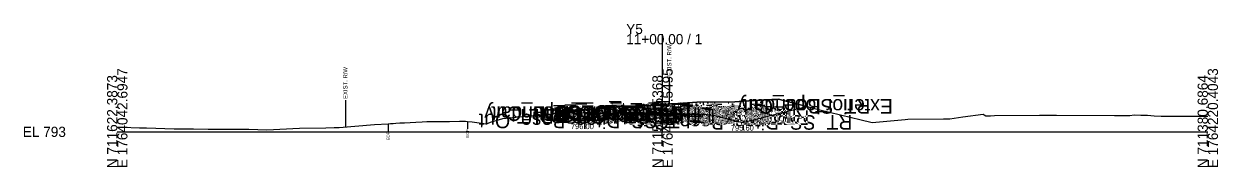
# Model space of a CAD drawing. Extents: x -26 to 303, y -10 to 4039.
# Drawn here: x -25.7 to 302.8, y 990.3 to 1029.7 of the extents above; entities that cross this region are included whole.
import ezdxf

# ---------------------------------------------------------------- set-up
doc = ezdxf.new("R2010")
doc.units = 0
for name, color, linetype in [('Default', 7, 'Continuous'), ('Exist Cross Section Cell', 7, 'Continuous'), ('Exist XS Center Line Elevation Label', 7, 'Continuous'), ('Exist XS Ground Line', 7, 'Continuous'), ('Old_Level_10', 7, 'Continuous'), ('Prop CMT Pvmt Course 1', 7, 'Continuous'), ('Prop CMT Pvmt Course 3', 7, 'Continuous'), ('Prop CMT Pvmt Surface', 7, 'Continuous'), ('Prop CMT Pvmt Surface Shoulder', 7, 'Continuous'), ('Prop CMT Shld Paved Course 1', 7, 'Continuous'), ('Prop CMT Shld Paved Course 3', 7, 'Continuous'), ('Prop CMT Slope Grass', 7, 'Continuous'), ('Prop CMT Subgrade Earthwork', 7, 'Continuous'), ('Prop XS Ditch Standard Text', 7, 'Continuous'), ('Prop XS Earthwork Shape', 7, 'Continuous'), ('Prop XS SE Text', 7, 'Continuous'), ('Prop XS Side Slope Text', 7, 'Continuous'), ('Scratch_Level_4', 7, 'Continuous')]:
    doc.layers.add(name, color=color, linetype=linetype)

msp = doc.modelspace()

# ---------------------------------------------------------------- linework, layer by layer
at = {"layer": 'Exist Cross Section Cell'}
for p, q in [((150, 1000), (150, 1026.88)), ((0, 1000), (150, 1000)), ((150, 1000), (300, 1000))]:
    msp.add_line(p, q, dxfattribs=at)
at = {"layer": 'Exist XS Ground Line'}
msp.add_lwpolyline([(0, 1001.28), (1.44, 1001.25), (6.11, 1001.13), (8.01, 1001.09), (15.68, 1000.83), (16.48, 1000.83), (18.35, 1000.8), (19.25, 1000.79), (20.98, 1000.79), (25.01, 1000.76), (28.82, 1000.72), (31.26, 1000.7), (36.22, 1000.73), (41.18, 1000.54), (50.12, 1001.02), (57.39, 1001.12), (59.71, 1001.15), (61.08, 1001.2), (70.77, 1002), (74.52, 1002.17), (75.19, 1002.26), (75.88, 1002.34), (76.67, 1002.38), (77.75, 1002.44), (78.46, 1002.48), (78.99, 1002.51), (82.09, 1002.69), (83.83, 1002.73), (85.19, 1002.8), (85.61, 1002.81), (86.19, 1002.82), (88.3, 1002.85), (89.19, 1002.86), (90.41, 1002.87), (91.4, 1002.88), (94.15, 1002.91), (94.5, 1002.92), (95.4, 1002.9), (95.76, 1002.89), (96.34, 1002.88), (97.66, 1002.71), (100.22, 1002.42), (101.54, 1002.23), (102.67, 1002.62), (106.11, 1003.7), (112.3, 1004.31), (117.81, 1004.72), (124.32, 1005.53), (132.58, 1006.42), (140.43, 1007.06), (146.69, 1007.29), (150, 1007.53), (155.55, 1007.92), (156.88, 1007.97), (157.19, 1007.97), (157.49, 1008.01), (158.26, 1008.06), (159.48, 1008.12), (169.88, 1008.25), (172.18, 1008.47), (180.06, 1008.86), (180.75, 1008.9), (181.17, 1008.92), (181.91, 1008.96), (192.88, 1006.16), (202.01, 1003.9), (204.27, 1003.39), (207.65, 1002.55), (216.79, 1003.38), (217.46, 1003.44), (227.27, 1003.58), (229.06, 1003.59), (232.62, 1004.1), (238.16, 1004.89), (238.5, 1004.67), (238.96, 1004.39), (240.21, 1004.42), (241.36, 1004.45), (253.73, 1004.56), (258.38, 1004.57), (274.32, 1004.49), (278.54, 1004.53), (279.73, 1004.64), (281.55, 1004.61), (283.45, 1004.54), (285.23, 1004.39), (287.19, 1004.34), (289.95, 1004.32), (291.6, 1004.33), (293.39, 1004.29), (300, 1004.29)], dxfattribs=at)
at = {"layer": 'Old_Level_10'}
for p, q in [((151.85, 1015.06), (151.85, 1007.66)), ((62.74, 1008.74), (62.74, 1001.34)), ((74.52, 1002.17), (74.52, 1000.12)), ((96.34, 1002.88), (96.34, 1000.83))]:
    msp.add_line(p, q, dxfattribs=at)
at = {"layer": 'Prop CMT Pvmt Course 1'}
for points in [[(150, 1005.12), (140, 1005.32)], [(140, 1005.32), (140, 1005.07)], [(140, 1005.07), (150, 1004.87)], [(150, 1004.87), (150, 1005.12)], [(150, 1005.12), (160, 1004.92)], [(160, 1004.67), (150, 1004.87)], [(160, 1004.92), (160, 1004.67)]]:
    msp.add_lwpolyline(points, dxfattribs=at)
msp.add_lwpolyline([(150, 1004.87), (150, 1005), (150, 1005), (150, 1004.87)], close=True, dxfattribs=at)
at = {"layer": 'Prop CMT Pvmt Course 3'}
for points in [[(150, 1004.87), (140, 1005.07)], [(140, 1005.07), (140, 1004.66)], [(159.99, 1004.26), (149.99, 1004.46)], [(150, 1004.46), (150, 1004.87)], [(150, 1004.87), (160, 1004.67)], [(160, 1004.67), (160, 1004.26)]]:
    msp.add_lwpolyline(points, dxfattribs=at)
at = {"layer": 'Prop CMT Pvmt Surface'}
for points in [[(150, 1005.12), (140, 1005.32)], [(150, 1005.12), (160, 1004.92)]]:
    msp.add_lwpolyline(points, dxfattribs=at)
at = {"layer": 'Prop CMT Pvmt Surface Shoulder'}
for points in [[(140, 1005.32), (140, 1005.32)], [(160, 1004.92), (160, 1004.92)]]:
    msp.add_lwpolyline(points, dxfattribs=at)
at = {"layer": 'Prop CMT Shld Paved Course 1'}
for points in [[(140, 1005.32), (139.74, 1005.07)], [(140, 1005.32), (140, 1005.32)], [(140, 1005.07), (140, 1005.32)], [(139.74, 1005.07), (140, 1005.07)], [(160, 1004.92), (160, 1004.92)], [(160, 1004.92), (160.26, 1004.67)], [(160, 1004.67), (160, 1004.92)], [(160.26, 1004.67), (160, 1004.67)]]:
    msp.add_lwpolyline(points, dxfattribs=at)
at = {"layer": 'Prop CMT Shld Paved Course 3'}
for points in [[(139.74, 1005.07), (139.32, 1004.64)], [(139.32, 1004.64), (140, 1004.66)], [(140, 1005.07), (139.74, 1005.07)], [(140, 1004.74), (140, 1005.07)], [(160, 1004.67), (160.26, 1004.67)], [(160, 1004.34), (160, 1004.67)], [(160.68, 1004.24), (160, 1004.26)], [(160.26, 1004.67), (160.68, 1004.24)]]:
    msp.add_lwpolyline(points, dxfattribs=at)
at = {"layer": 'Prop CMT Slope Grass'}
for points in [[(140, 1005.32), (136, 1005), (128, 1003), (120.02, 1005)], [(160, 1004.92), (164, 1004.6), (172, 1002.6), (189.59, 1007)]]:
    msp.add_lwpolyline(points, dxfattribs=at)
at = {"layer": 'Prop CMT Subgrade Earthwork'}
for p, q in [((138.76, 1005.22), (139.32, 1004.64)), ((139.32, 1004.64), (140, 1004.66)), ((149.99, 1004.46), (140, 1004.66)), ((149.99, 1004.46), (160, 1004.26)), ((160, 1004.26), (160.68, 1004.24)), ((161.28, 1004.82), (160.68, 1004.24))]:
    msp.add_line(p, q, dxfattribs=at)
at = {"layer": 'Prop XS Earthwork Shape'}
for points in [[(164, 1004.6), (172, 1002.6), (189.59, 1007), (181.91, 1008.96), (181.17, 1008.92), (180.75, 1008.9), (180.06, 1008.86), (172.18, 1008.47), (169.88, 1008.25), (159.48, 1008.12), (158.26, 1008.06), (157.49, 1008.01), (157.19, 1007.97), (156.88, 1007.97), (155.55, 1007.92), (150, 1007.53), (146.69, 1007.29), (140.43, 1007.06), (132.58, 1006.42), (124.32, 1005.53), (120.02, 1005), (128, 1003), (136, 1005), (138.76, 1005.22), (140, 1005.32), (150, 1005.12), (160, 1004.92), (161.28, 1004.82)], [(161.28, 1004.82), (160.68, 1004.24), (160, 1004.26), (149.99, 1004.46), (140, 1004.66), (139.32, 1004.64), (138.76, 1005.22), (140, 1005.32), (150, 1005.12), (160, 1004.92)]]:
    msp.add_lwpolyline(points, close=True, dxfattribs=at)

# ---------------------------------------------------------------- texts
at = {"layer": 'Default'}
msp.add_text('-', height=0.0001, dxfattribs=at).set_placement((0, 1000))
at = {"layer": 'Exist Cross Section Cell'}
for s, p in [('Y5', (140, 1026.88)), ('11+00.00 / 1', (140, 1024.08)), ('EL 793', (-26, 998.6))]:
    msp.add_text(s, height=2.8, dxfattribs=at).set_placement(p)
for s, p in [('N 711622.3873', (0, 990)), ('E 1764042.6947', (2.8, 990)), ('N 711501.5368', (150, 990)), ('E 1764131.5495', (152.8, 990)), ('N 711380.6864', (300, 990)), ('E 1764220.4043', (302.8, 990))]:
    msp.add_text(s, height=2.8, rotation=90, dxfattribs=at).set_placement(p)
at = {"layer": 'Exist XS Center Line Elevation Label'}
msp.add_text('800.53', height=1, dxfattribs=at).set_placement((147.88, 1005.53))
at = {"layer": 'Old_Level_10'}
for s, height, p in [('EXIST. R/W', 1.181, (152.44, 1015.36)), ('EXIST. R/W', 1.181, (63.33, 1009.04)), ('EOP', 0.787, (74.91, 997.72)), ('EOP', 0.787, (96.73, 998.43))]:
    msp.add_text(s, height=height, rotation=90, dxfattribs=at).set_placement(p)
at = {"layer": 'Prop XS Ditch Standard Text'}
for s, p in [('796.00', (124.78, 1000.75)), ('795.60', (168.78, 1000.35))]:
    msp.add_text(s, height=1.5, dxfattribs=at).set_placement(p)
at = {"layer": 'Prop XS SE Text'}
for p in [(142.4, 1006.28), (152.4, 1006.08)]:
    msp.add_text('0.020', height=1.5, rotation=358.8542, dxfattribs=at).set_placement(p)
at = {"layer": 'Prop XS Side Slope Text'}
for rotation, p in [(345.9638, (123.04, 1005.02)), (14.0362, (130.66, 1004.44)), (345.9638, (167.03, 1004.62)), (14.0362, (179.46, 1005.24))]:
    msp.add_text('4:1', height=1.5, rotation=rotation, dxfattribs=at).set_placement(p)
at = {"layer": 'Scratch_Level_4'}
for s, p in [('Exterior Boundary', (213.37, 1009)), ('RT_Slope_Cut', (207.16, 1009)), ('LT_SS_Ditch_Base_Out', (157.73, 1005)), ('Exterior Boundary', (143.8, 1007)), ('LT_Slope_Cut', (137.09, 1007)), ('LT_Sub_OSS_DLT', (156.01, 1006.27)), ('LT_Sub_Trench_Out', (164.51, 1006.39)), ('LT_GS_OS_CTL', (155.62, 1007)), ('LT_PS3_Shelf_Out', (163.59, 1006.73)), ('LT_PV1_OEOT', (157.63, 1007.32)), ('LT_PS1_OEOP', (157.9, 1007.32)), ('LT_PS3_OEOP', (158.35, 1006.73)), ('LT_PS2_OEOP', (158.66, 1007.07)), ('LT_PV2_OEOT', (158.64, 1007.07)), ('LT_PV3_OEOT', (158.67, 1006.74)), ('LT_Sub_OEOT', (158.11, 1006.41)), ('RT_PV1_OEEOP', (170.2, 1007)), ('LT_PV1_OEEOP', (169.7, 1007)), ('RT_PV2_OEEOP', (171.21, 1006.87)), ('RT_PV3_OEEOP', (171.24, 1006.54)), ('RT_Sub_OEEOP', (170.67, 1006.21)), ('LT_PV2_OEEOP', (170.71, 1006.87)), ('LT_PV3_OEEOP', (170.74, 1006.54)), ('LT_Sub_OEEOP', (170.17, 1006.21)), ('RT_PV1_IEEOP', (169.32, 1007)), ('LT_PV1_IEEOP', (168.82, 1007)), ('RT_PV2_IEEOP', (170.33, 1006.87)), ('LT_PV2_IEEOP', (169.82, 1006.87)), ('RT_Sub_Trench_Out', (186.88, 1005.99)), ('PV1_PGL', (160.68, 1007.12)), ('PV2_PGL', (161.68, 1006.87)), ('RT_PS3_Shelf_Out', (185.28, 1006.33)), ('RT_PV1_OEOT', (178.14, 1006.92)), ('RT_PS1_OEOP', (178.41, 1006.92)), ('RT_PV2_OEOT', (179.15, 1006.67)), ('RT_PV3_OEOT', (179.18, 1006.34)), ('RT_Sub_OEOT', (178.61, 1006.01)), ('RT_PS2_OEOP', (179.67, 1006.67)), ('RT_PS3_OEOP', (180.04, 1006.33)), ('RT_GS_OS_CTL', (184.12, 1006.6)), ('RT_SS_Ditch_Base_Out', (202.23, 1004.6)), ('RT_Sub_OSS_DLT', (190.4, 1005.87))]:
    msp.add_text(s, height=4, rotation=180, dxfattribs=at).set_placement(p)

doc.saveas('drawing.dxf')
